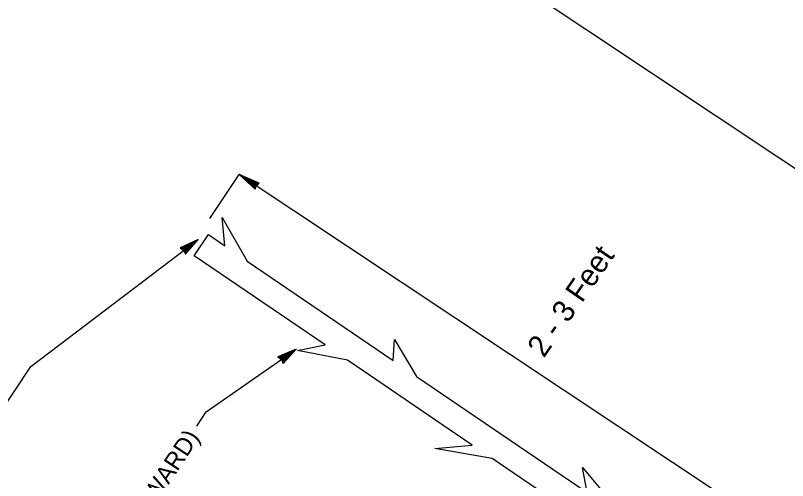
# Model space of a CAD drawing. Extents: x 561231 to 564935, y 589159 to 602519.
# Drawn here: x 564136 to 564264, y 589581.1 to 589658.2 of the extents above; entities that cross this region are included whole.
import ezdxf

# ---------------------------------------------------------------- set-up
doc = ezdxf.new("R2010")
doc.units = 0
doc.layers.add('Old_Level_1', color=7, linetype='Continuous')

msp = doc.modelspace()

# ---------------------------------------------------------------- linework, layer by layer
at = {"layer": 'Old_Level_1'}
for p, q in [((564168.23, 589624.52), (564173.1, 589631.85)), ((564270.3, 589567.33), (564173.1, 589631.85)), ((564176.42, 589630.4), (564173.1, 589631.85)), ((564173.1, 589631.85), (564175.74, 589629.39)), ((564175.88, 589630.02), (564173.1, 589631.85)), ((564175.74, 589629.39), (564175.88, 589630.02)), ((564175.88, 589630.02), (564176.42, 589630.4)), ((564138.53, 589600.01), (564166.28, 589621.07)), ((564166.28, 589621.07), (564163.3, 589619.66)), ((564163.9, 589619.26), (564166.28, 589621.07)), ((564164.2, 589618.61), (564166.28, 589621.07)), ((564163.3, 589619.66), (564163.9, 589619.26)), ((564163.9, 589619.26), (564164.2, 589618.61)), ((564167.62, 589592.52), (564182.55, 589602.92)), ((564182.55, 589602.92), (564179.48, 589601.62)), ((564180.08, 589601.21), (564182.55, 589602.92)), ((564180.35, 589600.55), (564182.55, 589602.92)), ((564179.48, 589601.62), (564180.08, 589601.21)), ((564131.66, 589589.72), (564138.53, 589600.01)), ((564180.08, 589601.21), (564180.35, 589600.55)), ((564166.04, 589590.17), (564167.62, 589592.52))]:
    msp.add_line(p, q, dxfattribs=at)
for points in [[(564040.89, 589558.02), (564144.12, 589713.34), (564327.69, 589591.34), (564224.45, 589436.03)], [(564165.6, 589618.38), (564167.98, 589621.87), (564170.71, 589620.01), (564170.29, 589624.7), (564174.43, 589617.48), (564198.6, 589601.03), (564198.82, 589604.52), (564202.5, 589598.37), (564230.8, 589579.15), (564230.03, 589583.32), (564237.02, 589574.94), (564262.87, 589557.36), (564252.59, 589559.26), (564240.21, 589567.68), (564231.23, 589570.02), (564234.83, 589571.31), (564215.01, 589584.78), (564205.55, 589586.43), (564211.71, 589587.03), (564191.05, 589601.08), (564182.77, 589602.7), (564187.33, 589603.61)]]:
    msp.add_lwpolyline(points, close=True, dxfattribs=at)
for points in [[(564173.1, 589631.85), (564176.34, 589630.41), (564173.3, 589631.72), (564176.26, 589630.32), (564173.69, 589631.47), (564176.2, 589630.28), (564174.15, 589631.17), (564176.14, 589630.22), (564174.52, 589630.9), (564176.04, 589630.19), (564174.93, 589630.64), (564176, 589630.13), (564175.42, 589630.35), (564175.93, 589630.08), (564175.7, 589630.15), (564175.87, 589630.06), (564175.7, 589630.15), (564175.85, 589629.99), (564175.41, 589630.33), (564175.85, 589629.89), (564174.93, 589630.64), (564175.83, 589629.82), (564174.55, 589630.89), (564175.8, 589629.71), (564174.15, 589631.17), (564175.76, 589629.6), (564173.7, 589631.46), (564175.76, 589629.49), (564173.3, 589631.72), (564175.72, 589629.45), (564173.1, 589631.85)], [(564166.28, 589621.07), (564164.2, 589618.68), (564166.09, 589620.91), (564164.15, 589618.79), (564165.78, 589620.67), (564164.11, 589618.88), (564165.39, 589620.38), (564164.07, 589618.96), (564165.06, 589620.13), (564164.06, 589619.04), (564164.7, 589619.88), (564163.99, 589619.12), (564164.34, 589619.55), (564163.95, 589619.2), (564164.07, 589619.39), (564163.95, 589619.26), (564164.07, 589619.39), (564163.89, 589619.32), (564164.32, 589619.57), (564163.8, 589619.35), (564164.7, 589619.88), (564163.72, 589619.41), (564165.04, 589620.13), (564163.62, 589619.47), (564165.39, 589620.38), (564163.53, 589619.55), (564165.76, 589620.66), (564163.4, 589619.6), (564166.09, 589620.91), (564163.36, 589619.65), (564166.28, 589621.07)], [(564182.55, 589602.92), (564180.37, 589600.64), (564182.35, 589602.77), (564180.31, 589600.74), (564182.03, 589602.55), (564180.29, 589600.81), (564181.63, 589602.26), (564180.24, 589600.9), (564181.28, 589602.03), (564180.24, 589601), (564180.91, 589601.79), (564180.16, 589601.06), (564180.52, 589601.5), (564180.14, 589601.14), (564180.25, 589601.33), (564180.12, 589601.2), (564180.25, 589601.33), (564180.07, 589601.28), (564180.52, 589601.49), (564179.97, 589601.31), (564180.91, 589601.79), (564179.89, 589601.35), (564181.25, 589602.02), (564179.8, 589601.43), (564181.63, 589602.26), (564179.71, 589601.51), (564182.01, 589602.52), (564179.6, 589601.56), (564182.35, 589602.77), (564179.57, 589601.62), (564182.55, 589602.92)]]:
    msp.add_lwpolyline(points, dxfattribs=at)

# ---------------------------------------------------------------- texts
for s, height, rotation, p in [('2 - 3 Feet', 3.634, 55.2558, (564223.59, 589601.33)), ('BUDS (FACING UPWARD)', 2.9074, 56.4198, (564140.36, 589548.73))]:
    msp.add_text(s, height=height, rotation=rotation, dxfattribs=at).set_placement(p)

doc.saveas('drawing.dxf')
